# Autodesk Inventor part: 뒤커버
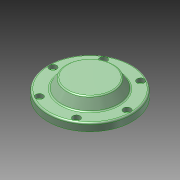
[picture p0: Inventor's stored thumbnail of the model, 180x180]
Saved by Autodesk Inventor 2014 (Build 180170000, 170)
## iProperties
Created: 2013-01
Part Number: 뒤커버
Document SubType Name: Modeling
Designer: 한국산업디자인학원[gmhk.co.kr]
Density: 2.71 g/cm^3
Material: 알루미늄 6061
Mass: 398.51 g
Surface Area: 273.589 cm^2
Volume: 147.052 cm^3
Appearance: 알루미늄 - 평지(1)
Author: 한국산업디자인학원[gmhk.co.kr]
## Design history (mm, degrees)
sketch "스케치2"
  geometry: L1 (-55, 0)-(55, 0) reference; L2 (35.98, -6)-(-35.98, -6) reference; L3 (-42.5, -25)-(-42.5, 0) reference; L4 (-37, -6)-(-37, 0); L5 (-55, 0)-(-55, 10); L6 (-55, 10)-(-37.5, 10); L7 (-37, -6)-(-42.5, -6); L8 (-37.5, 10)-(-29.994, 23); L9 (-29.994, 23)-(0, 23); L10 (-55, 0)-(-42.5, 0); L11 (-42.5, -6)-(-42.5, 0); L12 (0, 0)-(0, 23); L13 (0, 0)-(-37, 0)
  constraints: 22 end point, 4 perpendicular, 3 collinear, 2 parallel, 2 point on line, 1 vertical, 2 other
  dimensions: "d2" = 10 distance of L1.start L5.end; "d4" = 120 deg angle of L8 L6; "d5" = 13 distance between parallel lines of L6 L9; "d6" = 74 diameter of L4 L12; "d7" = 75 diameter of L6.end L12
revolve "회전1" sketch "스케치2" stored, may be unused: angle "d8" = 90 deg
fillet "모깎기1" dims "d9" = 2
sketch "스케치3"
  geometry: C1 r 2.067 at (48.5, 0) reference; 1 further point
hole "구멍1" sketch "스케치3" at (48.5, 0) diameter "d10" = 5.5; stored, may be unused: countersink angle "d14" = 90 deg, drill point angle "d16" = 118 deg; dims "d11" = 6, "d12" = 9.5, "d13" = 5.4, "d15" = 8
fillet "모깎기2" dims "d20" = 3
chamfer "모따기1" distance "d21" = 1; stored, may be unused: second distance "d22" = 2, angle "d23" = 45 deg
node "솔리드1"
pattern_circular "원형 패턴1" dims angle "d18" = 360 deg
node "참조1"
node "참조2"
node "참조3"
